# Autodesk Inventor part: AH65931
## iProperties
Created: 2006-09
Part Number: AH65931
Cost Center: 0,03 kg
Material: 1.0116 S355 J2G3
Document SubType Name: Modeling
Designer: ahuetter
Authority: 3837,265 mm^3
SaveDate: 2006-09-28
SaveTime: 09:26
FileName: AH65931
TotalMass: 0,03 kg
TotalVolume: 3837,265 mm^3
Author: ahuetter
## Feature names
1. Drehung1 [Revolution]
2. Bohrung3 [Hole]
3. Fase1 [Chamfer]
4. Fase2 [Chamfer]
5. Extrusion2
6. Runde Anordnung1 [Circular Pattern]
7. Bohrung4 [Hole]
8. Runde Anordnung2 [Circular Pattern]
